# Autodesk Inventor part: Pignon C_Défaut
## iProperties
Shininess: 64.0
Length Units: 11269
Angle Units: 11279
Time Units: 11290
Mass Units: 11283
Length Display Precision: 3
Angle Display Precision: 2
Compacted: True
Part Number: Pignon C_Défaut
Document SubType Name: Modeling
Created: 2006-01
Material: Par défaut
Designer: Fricot
Density: 0.0
Volumn: 0.0
Area: 0.0
PropertySet Name: Model Information
Control State: 0
Master: False
Checked Out: False
Author: Fricot
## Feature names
1. Base1
